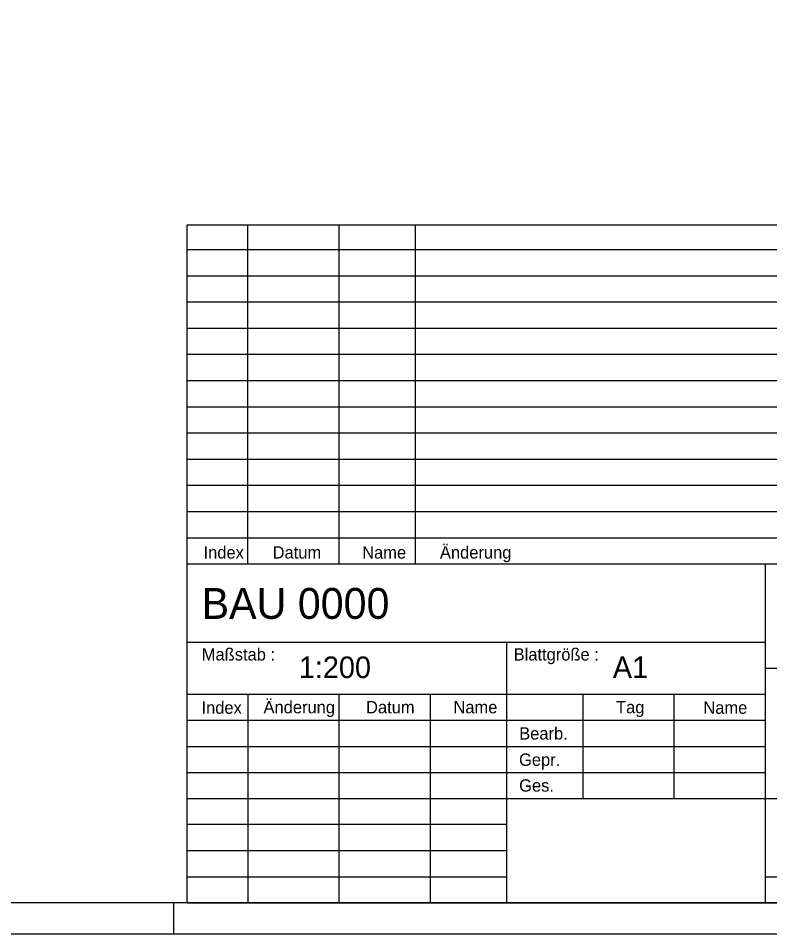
# Model space of a CAD drawing. Extents: x 0 to 168, y 0 to 119.
# Drawn here: x 126.15 to 150.53, y 0 to 29.7 of the extents above; entities that cross this region are included whole.
import ezdxf

# ---------------------------------------------------------------- set-up
doc = ezdxf.new("R2010")
doc.units = 0
doc.layers.add('90_Plankopf', color=7, linetype='Continuous')

msp = doc.modelspace()

# ---------------------------------------------------------------- linework, layer by layer
at = {"layer": '90_Plankopf'}
for p, q in [((131.624, 11.998), (131.624, 22.996)), ((131.624, 22.996), (167.2, 22.996)), ((133.6, 11.998), (133.6, 22.996)), ((136.565, 11.998), (136.565, 22.996)), ((139.036, 11.998), (139.036, 22.996)), ((131.624, 22.198), (167.2, 22.198)), ((131.624, 21.348), (167.2, 21.348)), ((131.624, 20.498), (167.2, 20.498)), ((131.624, 19.648), (167.2, 19.648)), ((131.624, 18.798), (167.2, 18.798)), ((131.624, 17.948), (167.2, 17.948)), ((131.624, 17.098), (167.2, 17.098)), ((131.624, 16.248), (167.2, 16.248)), ((131.624, 15.398), (167.2, 15.398)), ((131.624, 14.548), (167.2, 14.548)), ((131.624, 13.698), (167.2, 13.698)), ((131.624, 12.848), (167.2, 12.848)), ((131.624, 11.998), (167.2, 11.998)), ((131.624, 1), (131.624, 11.998)), ((131.624, 11.998), (167.2, 11.998)), ((150.4, 1), (150.4, 11.998)), ((131.624, 9.46), (150.4, 9.46)), ((142, 1), (142, 9.46)), ((150.4, 8.614), (167.2, 8.614)), ((131.624, 7.774), (150.4, 7.774)), ((133.6, 7.768), (133.6, 1)), ((136.565, 1), (136.565, 7.768)), ((139.53, 1), (139.53, 7.768)), ((144.471, 7.768), (144.471, 4.384)), ((147.436, 4.384), (147.436, 7.768)), ((131.624, 6.926), (150.4, 6.926)), ((131.624, 6.076), (150.4, 6.076)), ((131.624, 5.23), (150.4, 5.23)), ((131.624, 4.384), (150.4, 4.384)), ((131.624, 4.384), (150.4, 4.384)), ((142, 4.384), (150.4, 4.384)), ((150.4, 4.384), (167.2, 4.384)), ((142, 3.538), (131.624, 3.538)), ((142, 2.692), (131.624, 2.692)), ((131.624, 1.846), (142, 1.846)), ((150.4, 1.846), (167.2, 1.846)), ((131.2, 0), (131.2, 1)), ((167.2, 1), (131.624, 1)), ((131.624, 1), (142, 1)), ((133.96, 1), (167.2, 1)), ((133.96, 1), (167.2, 1))]:
    msp.add_line(p, q, dxfattribs=at)
for points in [[(0, 0), (168.2, 0), (168.2, 118.8), (0, 118.8)], [(5, 117.8), (167.2, 117.8), (167.2, 1), (5, 1)]]:
    msp.add_lwpolyline(points, close=True, dxfattribs=at)

# ---------------------------------------------------------------- texts
for s, height, p in [('Index', 0.4, (132.161, 12.171)), ('Datum', 0.4, (134.403, 12.171)), ('Name', 0.4, (137.308, 12.171)), ('Änderung', 0.4, (139.831, 12.171)), ('BAU 0000      ', 1, (132.098, 10.215)), ('Maßstab :', 0.4, (132.103, 8.863)), ('Blattgröße :', 0.39998, (142.223, 8.863)), ('1:200    ', 0.7, (135.252, 8.294)), ('A1       ', 0.7, (145.44, 8.294)), ('Index', 0.4, (132.094, 7.135)), ('Änderung', 0.4, (134.107, 7.15)), ('Datum', 0.4, (137.434, 7.15)), ('Name', 0.4, (140.269, 7.15)), ('Tag', 0.4, (145.545, 7.15)), ('Name', 0.4, (148.378, 7.135)), ('Bearb.', 0.4, (142.403, 6.298)), ('Gepr.', 0.4, (142.398, 5.446)), ('Ges.', 0.4, (142.401, 4.609))]:
    msp.add_text(s, height=height, dxfattribs=at).set_placement(p)

doc.saveas('drawing.dxf')
